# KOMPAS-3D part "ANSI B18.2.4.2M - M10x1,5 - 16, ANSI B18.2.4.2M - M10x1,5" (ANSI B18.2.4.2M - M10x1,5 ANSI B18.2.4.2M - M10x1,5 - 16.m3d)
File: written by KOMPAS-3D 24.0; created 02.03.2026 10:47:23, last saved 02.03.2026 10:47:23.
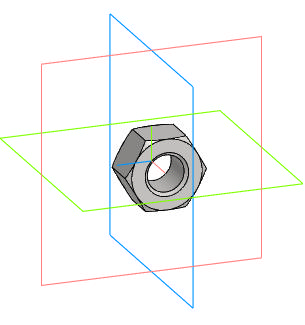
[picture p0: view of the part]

Document properties: Автор: R2D2; Полное имя файла: E:\Работа\Зайцев\GVWR3131M-2W-F-S Задвижка клиновая с выдвижным штоком DN.ru Ду50-200 Ру63\DN200\исходные материалы\ANSI B18.2.4.2M - M10x1,5 ANSI B18.2.4.2M - M10x1,5 - 16.m3d

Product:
- Body: Solid1  | qty 1
- Part/product: ANSI B18.2.4.2M - M10x1,5 - 16  | designation ANSI B18.2.4.2M - M10x1,5
    Комментарий: Типы метрических   шестигранных гаек   2
    additional columns: Сталь, мягкая

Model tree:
1. Solid1  (labels: Solid1)

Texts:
  ANSI B18.2.4.2M - M10x1,5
